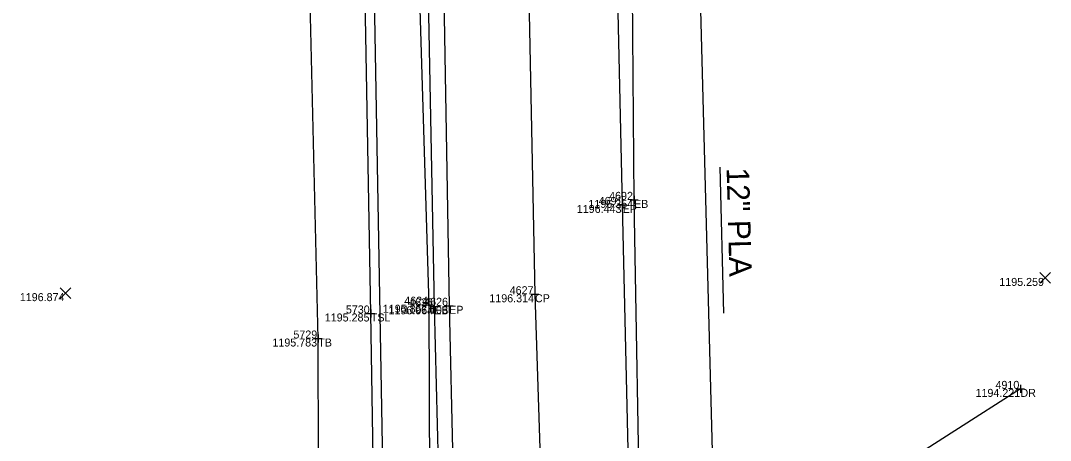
# Model space of a CAD drawing. Extents: x 2044996 to 2050343, y 455232 to 458054.
# Drawn here: x 2047581 to 2047709.6, y 456340.1 to 456392.6 of the extents above; entities that cross this region are included whole.
import ezdxf

# ---------------------------------------------------------------- set-up
doc = ezdxf.new("R2010")
doc.units = 0
for name, color, linetype in [('DR_X_Storm_Sewer', 7, 'Continuous'), ('DR_X_Text', 7, 'Continuous'), ('DT_X_Contour_Minor', 7, 'Continuous'), ('DT_X_Contour_Text', 7, 'Continuous'), ('DT_X_Spot_Elev', 7, 'Continuous'), ('DT_X_Triangles', 7, 'Continuous'), ('DT_X_Void', 7, 'Continuous'), ('PV_X_COP', 7, 'Continuous'), ('PV_X_Driveway', 7, 'Continuous'), ('PV_X_EOP', 7, 'Continuous'), ('PV_X_Shoulder_Aggregate', 7, 'Continuous'), ('SV_X_Break_Lines', 7, 'Continuous'), ('SV_X_Toe_of_Slope', 7, 'Continuous'), ('SV_X_Top_of_Bank', 7, 'Continuous')]:
    doc.layers.add(name, color=color, linetype=linetype)

msp = doc.modelspace()

# ---------------------------------------------------------------- linework, layer by layer
at = {"layer": 'DR_X_Storm_Sewer'}
for p, q in [((2047618.84, 456740.61), (2047628.62, 456202.21)), ((2047665.56, 456406.89), (2047667.64, 456327.27))]:
    msp.add_line(p, q, dxfattribs=at)
at = {"layer": 'DR_X_Text'}
msp.add_line((2047668.79, 456356.02), (2047668.32, 456374.24), dxfattribs=at)
at = {"layer": 'DT_X_Spot_Elev'}
for p, q in [((2047708.25, 456359.75), (2047709.58, 456361.09)), ((2047708.25, 456361.09), (2047709.58, 456359.75)), ((2047585.9, 456357.85), (2047587.24, 456359.19)), ((2047585.9, 456359.19), (2047587.24, 456357.85))]:
    msp.add_line(p, q, dxfattribs=at)
at = {"layer": 'DT_X_Void'}
for p, q in [((2047656.16, 456370.04), (2047656.16, 456369.04)), ((2047657.08, 456370.17), (2047658.08, 456370.17)), ((2047657.58, 456370.67), (2047657.58, 456369.67)), ((2047657.58, 456370.17), (2047657.58, 456370.17)), ((2047655.66, 456369.54), (2047656.66, 456369.54)), ((2047656.16, 456369.54), (2047656.16, 456369.54)), ((2047645.21, 456358.88), (2047645.21, 456357.88)), ((2047631.97, 456357.57), (2047631.97, 456356.57)), ((2047632.62, 456357.37), (2047632.62, 456356.37)), ((2047634.49, 456357.44), (2047634.49, 456356.44)), ((2047644.71, 456358.38), (2047645.71, 456358.38)), ((2047645.21, 456358.38), (2047645.21, 456358.38)), ((2047624.21, 456355.98), (2047625.21, 456355.98)), ((2047624.71, 456356.48), (2047624.71, 456355.48)), ((2047624.71, 456355.98), (2047624.71, 456355.98)), ((2047631.47, 456357.07), (2047632.47, 456357.07)), ((2047631.97, 456357.07), (2047631.97, 456357.07)), ((2047632.12, 456356.87), (2047633.12, 456356.87)), ((2047632.62, 456356.87), (2047632.62, 456356.87)), ((2047633.99, 456356.94), (2047634.99, 456356.94)), ((2047634.49, 456356.94), (2047634.49, 456356.94)), ((2047618.14, 456353.35), (2047618.14, 456352.35)), ((2047617.64, 456352.85), (2047618.64, 456352.85)), ((2047618.14, 456352.85), (2047618.14, 456352.85)), ((2047705.84, 456347.06), (2047705.84, 456346.06)), ((2047705.34, 456346.56), (2047706.34, 456346.56)), ((2047705.84, 456346.56), (2047705.84, 456346.56))]:
    msp.add_line(p, q, dxfattribs=at)
at = {"layer": 'PV_X_COP'}
msp.add_lwpolyline([(2047638.65, 456684.97), (2047639.72, 456638.63), (2047640.67, 456589.24), (2047641.66, 456540.18), (2047642.52, 456493.32), (2047643.71, 456444.37), (2047644.36, 456399.72), (2047645.21, 456358.38), (2047646.69, 456312.13), (2047647.16, 456279.14), (2047647.64, 456246.5), (2047648.01, 456224.8), (2047648.98, 456176.78), (2047649.64, 456128.98), (2047650.62, 456077.99), (2047651.48, 456030.79), (2047652.41, 455980.92), (2047652.55, 455976.29)], dxfattribs=at)
at = {"layer": 'PV_X_Driveway'}
msp.add_lwpolyline([(2047705.84, 456346.56), (2047681.25, 456330.83), (2047667.53, 456328.07), (2047658.72, 456325.15)], dxfattribs=at)
at = {"layer": 'PV_X_EOP'}
for p, q in [((2047656.16, 456369.54), (2047655.31, 456406.03)), ((2047633.74, 456399.39), (2047634.49, 456356.94)), ((2047657.13, 456325.52), (2047656.16, 456369.54)), ((2047634.49, 456356.94), (2047635.51, 456312.33))]:
    msp.add_line(p, q, dxfattribs=at)
at = {"layer": 'PV_X_Shoulder_Aggregate'}
for p, q in [((2047631.78, 456399.38), (2047632.62, 456356.87)), ((2047632.62, 456356.87), (2047633.7, 456312.63))]:
    msp.add_line(p, q, dxfattribs=at)
msp.add_lwpolyline([(2047664.76, 455980.11), (2047663.65, 456028.13), (2047662.66, 456078.84), (2047661.94, 456126.71), (2047661.18, 456172.4), (2047660.15, 456223.29), (2047659.21, 456276.46), (2047658.4, 456325.53), (2047657.58, 456370.17), (2047657.31, 456406.35), (2047656.24, 456454.32), (2047655.34, 456499.11), (2047654.47, 456545.86), (2047653.3, 456590.72), (2047651.94, 456638.93), (2047650.86, 456688.18)], dxfattribs=at)
at = {"layer": 'SV_X_Break_Lines'}
msp.add_lwpolyline([(2047625.21, 456638.95), (2047627.11, 456588.81), (2047628.32, 456540.51), (2047628.58, 456493.59), (2047629.46, 456445.22), (2047630.66, 456399.52), (2047631.97, 456357.07), (2047632.12, 456312.85), (2047632.56, 456284.1)], dxfattribs=at)
at = {"layer": 'SV_X_Toe_of_Slope'}
msp.add_lwpolyline([(2047627.42, 456261.1), (2047625.53, 456304.38), (2047624.71, 456355.98), (2047623.95, 456397.69), (2047623.34, 456452.18), (2047621.68, 456495.65), (2047623.55, 456542.59), (2047620.93, 456580.31), (2047618.38, 456635.97)], dxfattribs=at)
at = {"layer": 'SV_X_Top_of_Bank'}
msp.add_lwpolyline([(2047619.16, 456260.18), (2047618.27, 456307.13), (2047618.14, 456352.85), (2047617.01, 456400.11), (2047615.66, 456448.08), (2047612.43, 456496.09), (2047612.66, 456543.64), (2047611.43, 456577.89), (2047611.46, 456637.59)], dxfattribs=at)

# ---------------------------------------------------------------- texts
at = {"layer": 'DR_X_Text'}
msp.add_text('12" PLA', height=2.8, rotation=271.5003, dxfattribs=at).set_placement((2047669.14, 456374.16))
at = {"layer": 'DT_X_Contour_Minor'}
for s, p in [('1196.354', (2047651.88, 456369.17)), ('1196.443', (2047650.43, 456368.54)), ('1195.259', (2047703.2, 456359.42)), ('1196.874', (2047580.87, 456357.52)), ('1196.314', (2047639.51, 456357.38)), ('1195.285', (2047618.96, 456354.98)), ('1195.867', (2047626.2, 456356.07)), ('1196.064', (2047626.91, 456355.87)), ('1196.106', (2047628.75, 456355.94)), ('1195.783', (2047612.42, 456351.85)), ('1194.221', (2047700.23, 456345.56))]:
    msp.add_text(s, height=1, dxfattribs=at).set_placement(p)
at = {"layer": 'DT_X_Contour_Text'}
for s, p in [('EB', (2047657.58, 456369.17)), ('EP', (2047656.16, 456368.54)), ('CP', (2047645.21, 456357.38)), ('TSL', (2047624.71, 456354.98)), ('B', (2047631.97, 456356.07)), ('EB', (2047632.62, 456355.87)), ('EP', (2047634.49, 456355.94)), ('TB', (2047618.14, 456351.85)), ('DR', (2047705.84, 456345.56))]:
    msp.add_text(s, height=1, dxfattribs=at).set_placement(p)
at = {"layer": 'DT_X_Triangles'}
for s, p in [('4691', (2047653.16, 456369.54)), ('4692', (2047654.47, 456370.17)), ('4627', (2047642.05, 456358.38)), ('4624', (2047628.88, 456357.07)), ('4625', (2047629.49, 456356.87)), ('4626', (2047631.37, 456356.94)), ('5730', (2047621.59, 456355.98)), ('5729', (2047615.04, 456352.85)), ('4910', (2047702.72, 456346.56))]:
    msp.add_text(s, height=1, dxfattribs=at).set_placement(p)

doc.saveas('drawing.dxf')
